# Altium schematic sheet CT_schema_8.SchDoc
size 366 x 336 mm
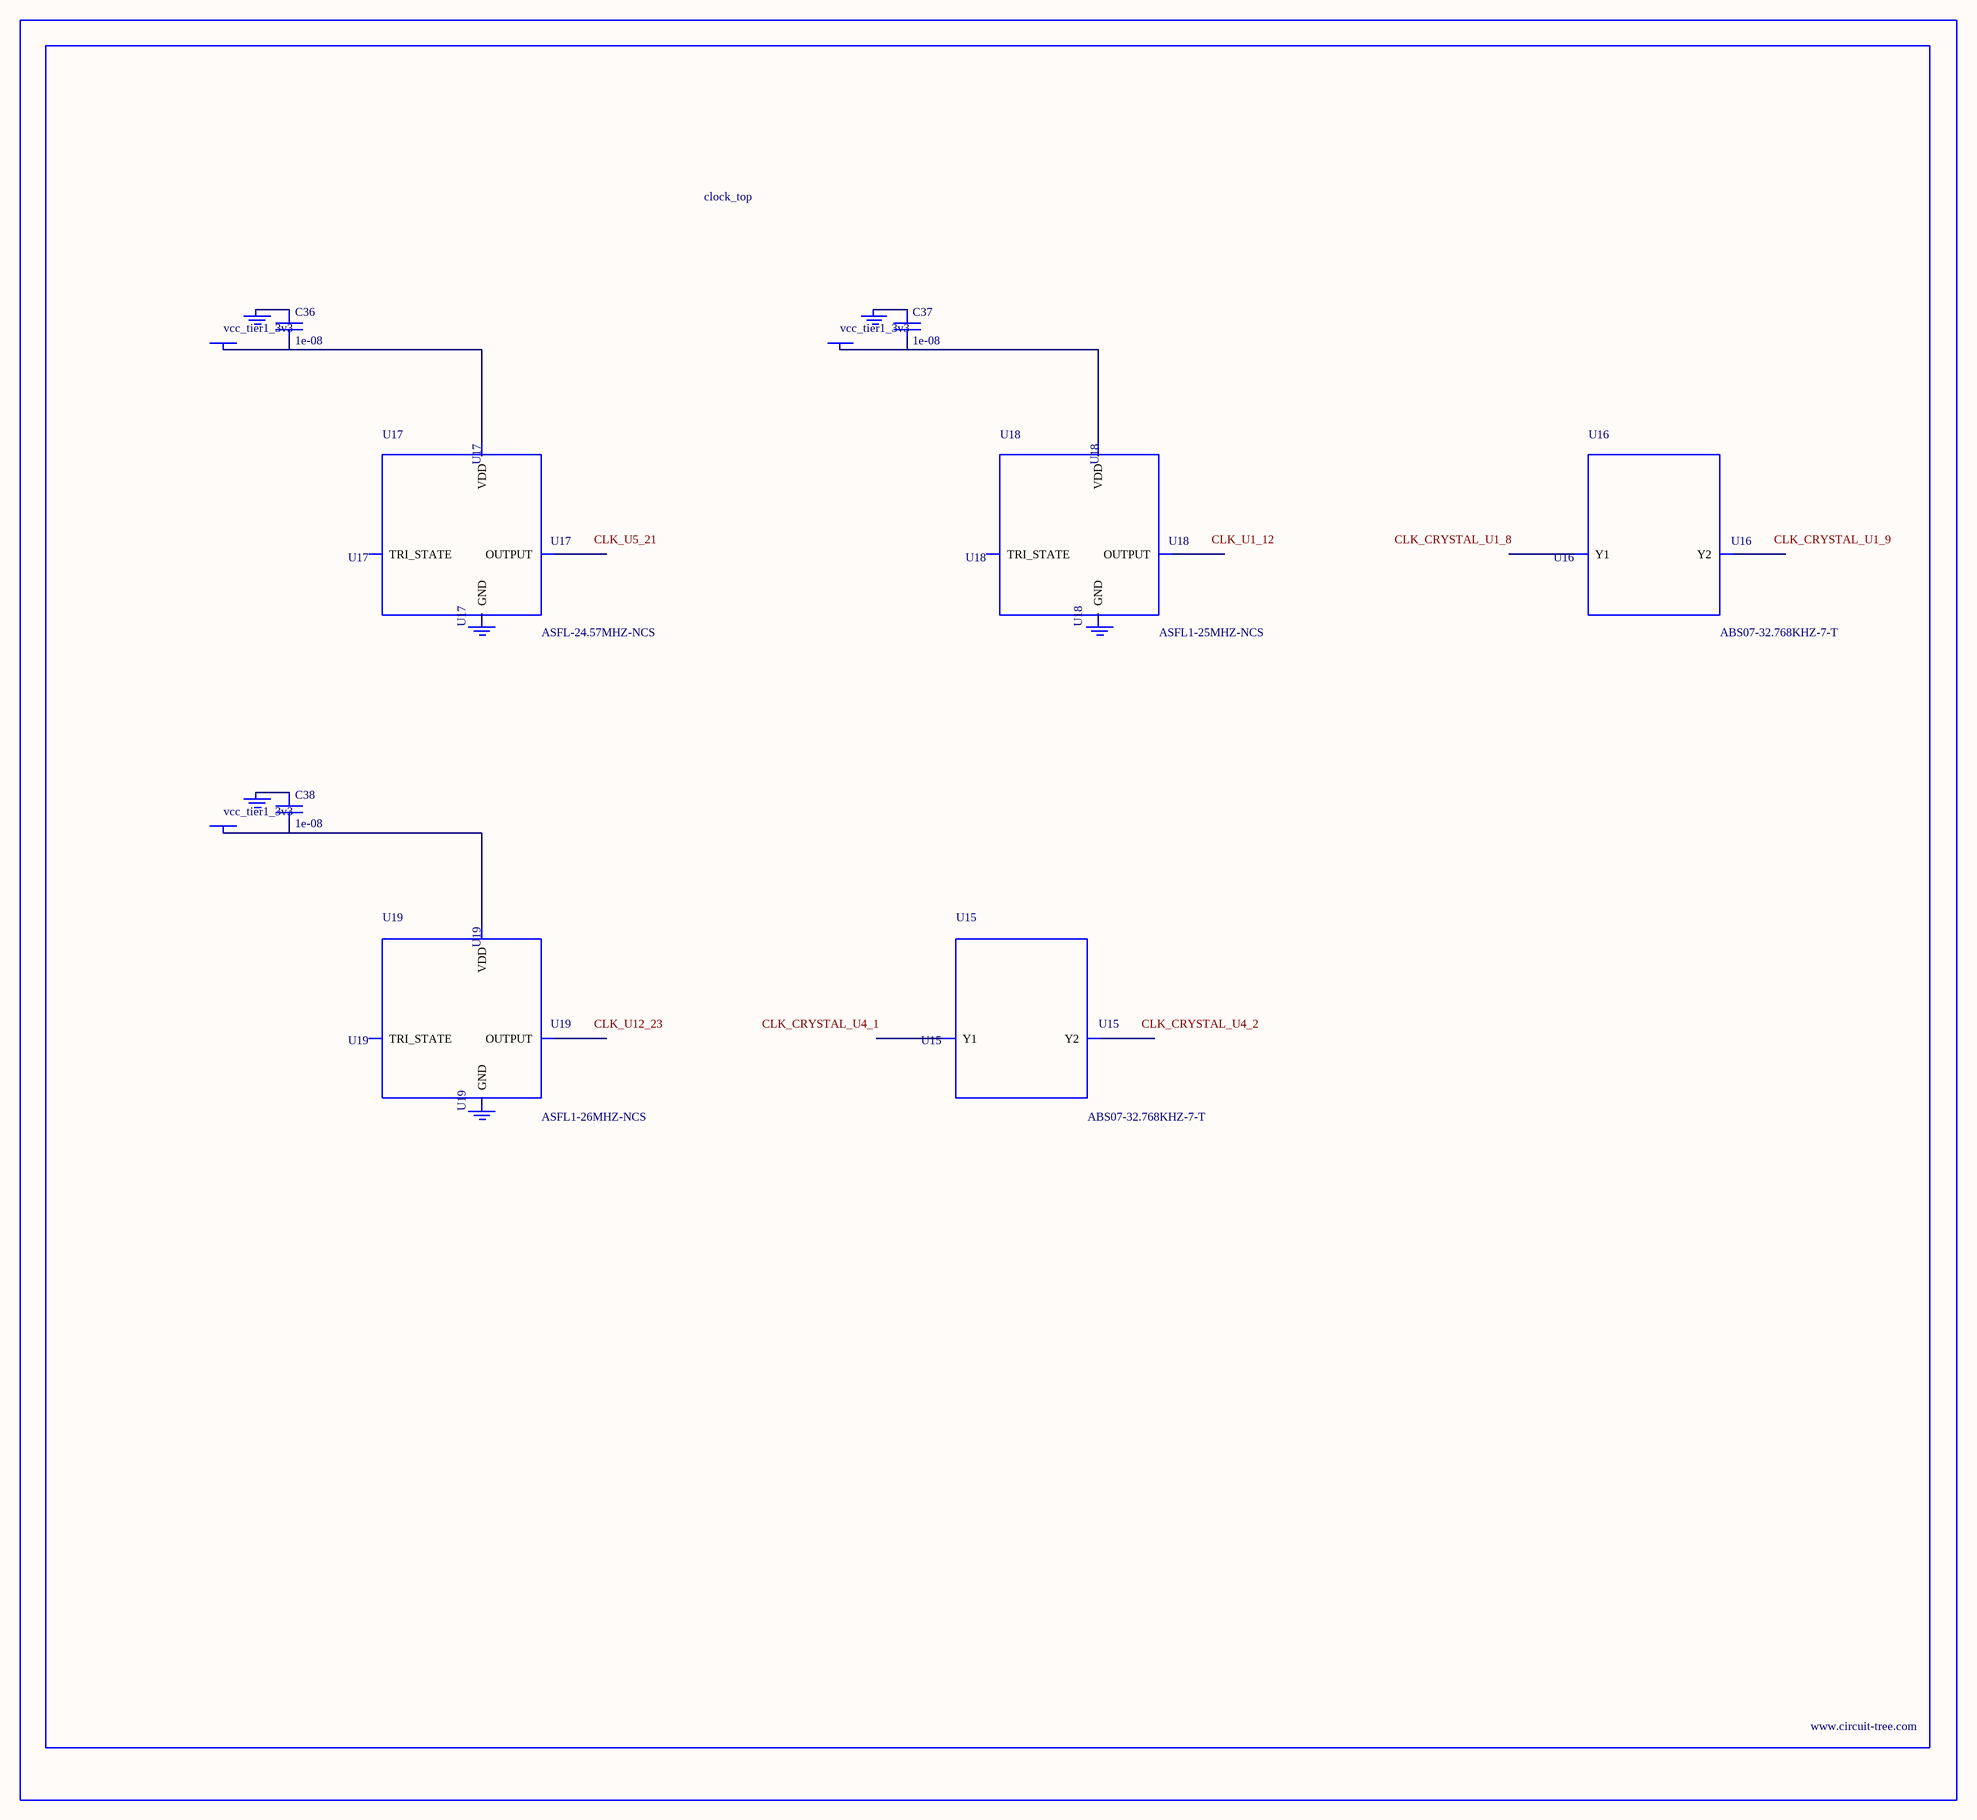
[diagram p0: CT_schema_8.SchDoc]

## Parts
BORDER7  (no value)
C36  1e-08  [C0402]
C37  1e-08  [C0402]
C38  1e-08  [C0402]
GND_INSTANCE_7_0  (no value)
GND_INSTANCE_7_1  (no value)
GND_INSTANCE_7_2  (no value)
GND_INSTANCE_7_3  (no value)
GND_INSTANCE_7_4  (no value)
GND_INSTANCE_7_5  (no value)
POWER_INSTANCE_7_0  vcc_tier1_3v3
POWER_INSTANCE_7_1  vcc_tier1_3v3
POWER_INSTANCE_7_2  vcc_tier1_3v3
U15  ABS07-32.768KHZ-7-T  [ABS07-32.768KHZ-7-T]
U16  ABS07-32.768KHZ-7-T  [ABS07-32.768KHZ-7-T]
U17  ASFL-24.57MHZ-NCS  [ASFL1]
U18  ASFL1-25MHZ-NCS  [ASFL1]
U19  ASFL1-26MHZ-NCS  [ASFL1]

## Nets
NetC36_1: C36.1 GND_INSTANCE_7_0.0(GND)
NetC36_2: C36.2 POWER_INSTANCE_7_0.0(PWR) U17.4(VDD)
NetC37_1: C37.1 GND_INSTANCE_7_2.0(GND)
NetC37_2: C37.2 POWER_INSTANCE_7_1.0(PWR) U18.4(VDD)
NetC38_1: C38.1 GND_INSTANCE_7_4.0(GND)
NetC38_2: C38.2 POWER_INSTANCE_7_2.0(PWR) U19.4(VDD)

Not connected (* = marked no-connect by the designer): GND_INSTANCE_7_1 0(GND); GND_INSTANCE_7_3 0(GND); GND_INSTANCE_7_5 0(GND); U15 1(Y1) 2(Y2); U16 1(Y1) 2(Y2); U17 1(TRI_STATE) 2(GND) 3(OUTPUT); U18 1(TRI_STATE) 2(GND) 3(OUTPUT); U19 1(TRI_STATE) 2(GND) 3(OUTPUT)

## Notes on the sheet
- Labels drawn without touching a wire or pin: CLK_CRYSTAL_U1_8, CLK_CRYSTAL_U1_9, CLK_CRYSTAL_U4_1, CLK_CRYSTAL_U4_2, CLK_U1_12, CLK_U5_21, CLK_U12_23

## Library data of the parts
BORDER7 = BORDER_PAGE7
C36-C38 = C0402C103K3RAC
GND_INSTANCE_7_0-GND_INSTANCE_7_5 = GND
POWER_INSTANCE_7_0-POWER_INSTANCE_7_2 = PWR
